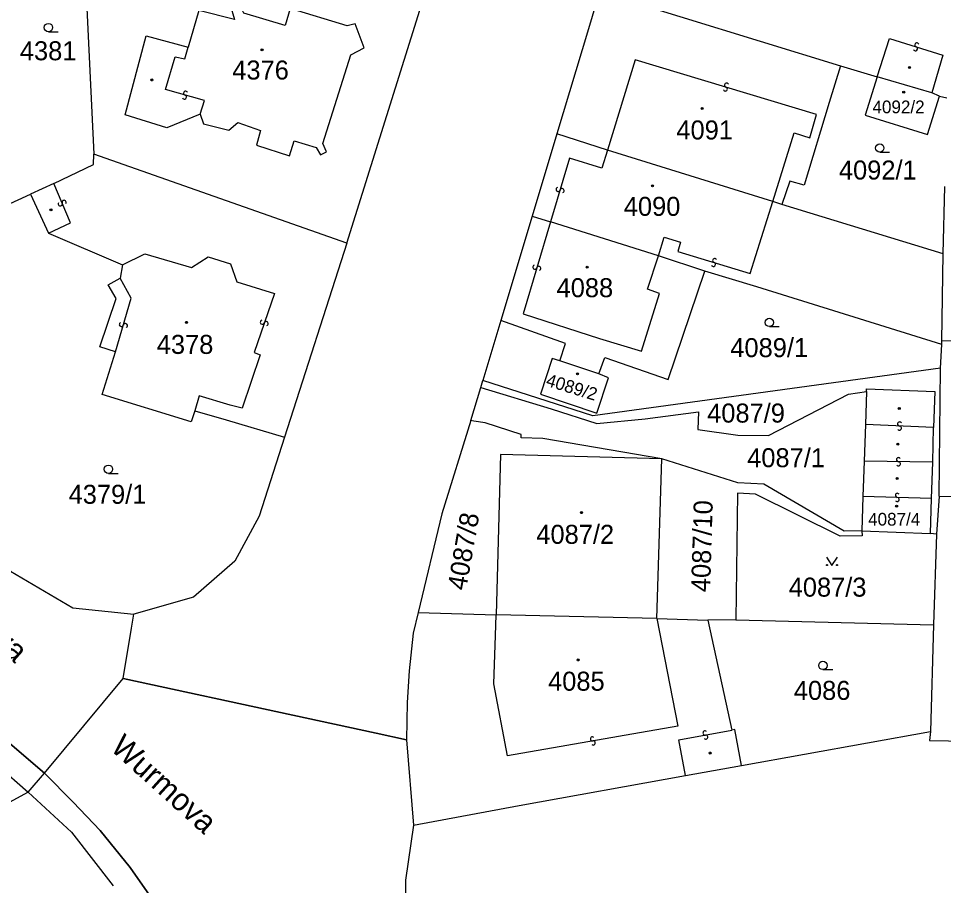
# Model space of a CAD drawing. Extents: x -600391 to -599491, y -1160176 to -1159402.
# Drawn here: x -600028.7 to -599946, y -1159661.1 to -1159583.6 of the extents above; entities that cross this region are included whole.
import ezdxf

# ---------------------------------------------------------------- set-up
doc = ezdxf.new("R2010")
doc.units = 0
for name, color, linetype in [('Level 1', 7, 'Continuous'), ('Level 11', 7, 'Continuous'), ('Level 13', 7, 'Continuous'), ('Level 3', 7, 'Continuous'), ('Level 4', 7, 'Continuous'), ('Level 5', 7, 'Continuous')]:
    doc.layers.add(name, color=color, linetype=linetype)

msp = doc.modelspace()

# ---------------------------------------------------------------- linework, layer by layer
at = {"layer": 'Level 1'}
for points in [[(-600084.15, -1159543.08), (-600050.91, -1159613.18), (-600035.85, -1159643.34), (-600030.3, -1159647.69), (-600026.35, -1159651.08), (-600019.33, -1159642.61)], [(-600023.03, -1159573.34), (-600021.95, -1159595.72)], [(-599976.73, -1159581.2), (-599977.73, -1159584.52), (-599980.55, -1159593.91)], [(-599976.73, -1159581.2), (-599955.2, -1159587.84)], [(-600012.45, -1159592.15), (-600012.13, -1159593.03), (-600009.89, -1159593.6), (-600009.07, -1159592.91), (-600007.05, -1159593.62), (-600007.4, -1159594.93), (-600004.46, -1159595.87), (-600004.05, -1159594.53), (-600002.07, -1159595.14), (-600001.69, -1159595.79), (-600001.14, -1159595.51), (-600001.48, -1159594.79), (-599998.96, -1159586.84), (-599997.79, -1159586.22), (-599998.6, -1159584.08), (-599999.3, -1159584.27), (-600004.4, -1159582.72), (-600004.84, -1159584.23), (-600008.53, -1159583.13), (-600009.05, -1159582.11), (-600009.77, -1159582.37), (-600009.37, -1159583.68), (-600012.57, -1159582.9), (-600013.52, -1159586.18)], [(-599999.32, -1159603.7), (-599992.79, -1159582.85)], [(-600012.45, -1159592.15), (-600015.43, -1159593.37), (-600019.16, -1159592.23), (-600017.27, -1159585.15), (-600013.52, -1159586.18)], [(-599955.2, -1159587.84), (-599956.21, -1159591.11), (-599958.46, -1159598.51), (-599959.72, -1159598.14), (-599960.43, -1159600.22)], [(-599955.2, -1159587.84), (-599951.92, -1159588.83)], [(-599951.92, -1159588.83), (-599952.98, -1159592.24), (-599947.42, -1159593.98), (-599946.34, -1159590.54)], [(-599947.03, -1159590.26), (-599951.92, -1159588.83)], [(-599946.34, -1159590.54), (-599947.03, -1159590.26)], [(-599946.34, -1159590.54), (-599945.69, -1159590.69)], [(-599980.55, -1159593.91), (-599982.75, -1159601.27)], [(-599976.03, -1159595.38), (-599980.55, -1159593.91)], [(-600025.51, -1159598.35), (-600021.98, -1159596.67), (-600021.95, -1159595.72)], [(-599999.32, -1159603.7), (-600021.95, -1159595.72)], [(-599961.25, -1159599.97), (-599976.03, -1159595.38)], [(-600025.51, -1159598.35), (-600027.62, -1159599.31)], [(-599946.01, -1159604.63), (-599945.86, -1159598.63)], [(-600042.97, -1159606.33), (-600027.62, -1159599.31)], [(-600027.62, -1159599.31), (-600026.01, -1159602.79)], [(-599960.43, -1159600.22), (-599961.25, -1159599.97)], [(-599946.01, -1159604.63), (-599960.43, -1159600.22)], [(-599982.75, -1159601.27), (-599985.57, -1159610.6)], [(-599982.75, -1159601.27), (-599981.12, -1159601.77)], [(-599971.48, -1159604.82), (-599981.12, -1159601.77)], [(-600026.01, -1159602.79), (-600019.37, -1159605.63)], [(-599999.32, -1159603.7), (-600004.9, -1159621.04)], [(-599967.32, -1159606.18), (-599971.48, -1159604.82)], [(-599946.13, -1159612.42), (-599946.01, -1159604.63)], [(-600019.37, -1159605.63), (-600019.6, -1159606.83)], [(-600042.97, -1159606.33), (-600032.49, -1159628.9), (-600029.4, -1159633.02), (-600023.82, -1159636.28), (-600018.38, -1159636.85)], [(-599976.8, -1159615.37), (-599976.27, -1159613.9), (-599970.6, -1159615.88), (-599967.32, -1159606.18)], [(-599946.13, -1159612.76), (-599962.69, -1159607.59), (-599967.32, -1159606.18)], [(-600020.01, -1159613.41), (-600021.42, -1159612.95), (-600019.96, -1159608.65), (-600020.66, -1159607.42), (-600019.6, -1159606.83)], [(-599985.57, -1159610.6), (-599987.16, -1159615.96)], [(-599980.29, -1159614.22), (-599979.77, -1159612.65), (-599985.57, -1159610.6)], [(-599946.13, -1159612.76), (-599946.13, -1159612.42)], [(-599919.38, -1159612.92), (-599946.13, -1159612.42)], [(-599946.25, -1159614.86), (-599946.13, -1159612.76)], [(-600012.92, -1159618.67), (-600013.26, -1159619.65), (-600021.2, -1159617.23), (-600020.01, -1159613.41)], [(-599980.29, -1159614.22), (-599980.98, -1159613.99), (-599982.01, -1159617.18), (-599976.98, -1159618.89), (-599975.95, -1159615.72), (-599976.8, -1159615.37)], [(-599946.25, -1159614.86), (-599977.34, -1159619.14), (-599987.16, -1159615.96)], [(-599976.8, -1159615.37), (-599980.29, -1159614.22)], [(-599946.38, -1159626.32), (-599946.25, -1159614.86)], [(-599987.35, -1159616.58), (-599987.16, -1159615.96)], [(-599988.26, -1159619.53), (-599987.35, -1159616.58)], [(-599987.35, -1159616.58), (-599981.06, -1159618.51), (-599976.97, -1159619.81), (-599972.67, -1159619.38), (-599967.9, -1159618.77), (-599967.94, -1159620.35), (-599964.37, -1159620.84), (-599961.64, -1159620.89), (-599954.47, -1159617.19), (-599952.88, -1159616.96)], [(-599952.88, -1159616.96), (-599952.95, -1159619.91)], [(-599952.88, -1159616.96), (-599952.87, -1159616.72), (-599946.77, -1159616.94), (-599946.88, -1159620.18)], [(-600012.92, -1159618.67), (-600010.13, -1159619.47), (-600004.9, -1159621.04)], [(-599988.26, -1159619.53), (-599990.83, -1159627.9), (-599992.95, -1159636.71)], [(-599971.17, -1159622.98), (-599981.82, -1159621.14), (-599983.76, -1159621.08), (-599983.74, -1159620.8), (-599986.96, -1159619.74), (-599987.99, -1159619.61), (-599988.26, -1159619.53)], [(-599952.95, -1159619.91), (-599953.09, -1159623.19)], [(-599946.94, -1159623.27), (-599946.88, -1159620.18)], [(-600004.9, -1159621.04), (-600007.17, -1159628.09), (-600009.35, -1159632.12), (-600013.05, -1159635.33), (-600018.38, -1159636.85)], [(-599971.17, -1159622.98), (-599985.6, -1159622.59), (-599985.99, -1159636.92)], [(-599971.62, -1159637.24), (-599971.17, -1159622.98)], [(-599953.29, -1159629.42), (-599954.88, -1159629.43), (-599962.05, -1159625.23), (-599964.39, -1159625.12), (-599971.17, -1159622.98)], [(-599953.09, -1159623.19), (-599953.19, -1159626.33)], [(-599947.05, -1159626.52), (-599946.94, -1159623.27)], [(-599953.29, -1159629.42), (-599953.27, -1159629.86), (-599955.22, -1159629.87), (-599962.81, -1159626.14), (-599964.41, -1159626.04), (-599964.56, -1159637.36)], [(-599953.19, -1159626.33), (-599953.29, -1159629.42)], [(-599946.38, -1159626.32), (-599946.62, -1159629.69)], [(-599946.38, -1159626.32), (-599930.01, -1159626.62)], [(-599947.15, -1159629.66), (-599947.05, -1159626.52)], [(-599953.29, -1159629.42), (-599947.15, -1159629.66)], [(-599946.62, -1159629.69), (-599947.15, -1159629.66)], [(-599946.62, -1159629.69), (-599946.88, -1159637.81)], [(-600019.33, -1159642.61), (-600018.59, -1159638.1), (-600018.38, -1159636.85)], [(-599992.95, -1159636.71), (-599993.39, -1159638.56), (-599993.77, -1159641.91), (-599993.94, -1159644.74), (-599994, -1159648.08)], [(-599992.95, -1159636.71), (-599985.99, -1159636.92)], [(-599971.62, -1159637.24), (-599985.99, -1159636.92)], [(-599971.62, -1159637.24), (-599967.07, -1159637.39)], [(-599964.56, -1159637.36), (-599967.07, -1159637.39)], [(-599967.07, -1159637.39), (-599964.9, -1159647.23)], [(-599964.56, -1159637.36), (-599946.88, -1159637.81)], [(-599946.88, -1159637.81), (-599947.14, -1159647.36)], [(-600015.71, -1159663.78), (-600018.7, -1159659.49), (-600021.39, -1159656.2), (-600023.79, -1159653.65), (-600026.35, -1159651.08), (-600019.33, -1159642.61), (-600004.15, -1159645.89), (-599996.7, -1159647.5), (-599994, -1159648.08), (-599993.37, -1159655.71)], [(-599994, -1159648.08), (-599996.7, -1159647.5), (-600004.15, -1159645.89), (-600019.33, -1159642.61)], [(-600026.35, -1159651.08), (-600030.3, -1159647.69), (-600035.85, -1159643.34)], [(-599993.37, -1159655.71), (-599983.92, -1159653.96), (-599969.05, -1159651.28), (-599964.06, -1159650.4), (-599947.14, -1159647.36), (-599947.25, -1159648.16), (-599930.29, -1159648.46), (-599924.07, -1159648.56), (-599921.27, -1159648.58), (-599903.15, -1159648.95)], [(-599964.06, -1159650.4), (-599964.63, -1159647.18), (-599964.9, -1159647.23)], [(-599964.06, -1159650.4), (-599947.14, -1159647.36)], [(-599947.14, -1159647.36), (-599947.25, -1159648.16), (-599930.29, -1159648.46)], [(-599994, -1159648.08), (-599993.37, -1159655.71), (-599983.92, -1159653.96), (-599969.05, -1159651.28)], [(-600030.57, -1159650.4), (-600027.83, -1159652.78)], [(-599969.05, -1159651.28), (-599964.06, -1159650.4)], [(-600027.83, -1159652.78), (-600026.35, -1159651.08)], [(-600026.35, -1159651.08), (-600023.79, -1159653.65), (-600021.39, -1159656.2), (-600018.7, -1159659.49), (-600015.71, -1159663.78), (-600012.85, -1159668.55), (-599985.71, -1159716.21)], [(-600027.83, -1159652.78), (-600030.16, -1159654.06), (-600037.5, -1159658.14)], [(-600027.83, -1159652.78), (-600023.93, -1159656.35), (-600020.23, -1159661.15)], [(-599993.37, -1159655.71), (-599994.09, -1159660.65), (-599994.05, -1159663.73)]]:
    msp.add_lwpolyline(points, dxfattribs=at)
at = {"layer": 'Level 13'}
for centre, start, end in [((-599948.383, -1159585.965), 19.84143, 251.93943), ((-599948.496, -1159586.315), 199.62697, 72.21697), ((-599965.495, -1159589.906), 200.58598, 72.68397), ((-599965.386, -1159589.554), 20.37152, 252.96152), ((-600013.852, -1159590.637), 201.44915, 73.54714), ((-600013.749, -1159590.283), 21.23469, 253.82469), ((-599980.446, -1159598.886), 110.46831, 343.05831), ((-599980.094, -1159598.995), 290.68276, 162.78076), ((-600024.6, -1159600.039), 329.96282, 202.55282), ((-600024.941, -1159600.18), 150.17728, 22.27527), ((-599982.526, -1159605.837), 110.53561, 343.12561), ((-599982.174, -1159605.944), 290.75007, 162.84807), ((-599966.554, -1159605.596), 200.30479, 72.89479), ((-599966.445, -1159605.244), 20.51925, 252.61725), ((-600006.884, -1159610.76), 108.36665, 340.95665), ((-600006.536, -1159610.881), 288.58111, 160.67911), ((-600019.487, -1159610.957), 111.2226, 343.32059), ((-600019.133, -1159611.062), 291.00814, 163.59814), ((-599949.911, -1159619.856), 34.61138, 267.20138), ((-599949.93, -1159620.224), 214.82584, 86.92383), ((-599950.017, -1159623.046), 36.41301, 269.00301), ((-599950.024, -1159623.414), 216.62746, 88.72546), ((-599950.113, -1159626.236), 35.38585, 267.97585), ((-599950.127, -1159626.604), 215.6003, 87.6983), ((-599977.371, -1159648.009), 47.06536, 279.65536), ((-599967.311, -1159647.478), 47.49741, 279.5954), ((-599967.248, -1159647.841), 227.28295, 99.87295), ((-599977.31, -1159648.372), 227.27981, 99.37781)]:
    msp.add_arc(centre, 0.184, start, end, dxfattribs=at)
at = {"layer": 'Level 3'}
for points in [[(-599951.92, -1159588.83), (-599950.83, -1159585.38), (-599946.05, -1159586.89), (-599947.03, -1159590.26)], [(-600012.45, -1159592.15), (-600012.06, -1159590.95), (-600015.53, -1159589.96), (-600014.69, -1159587.02), (-600013.8, -1159587.22), (-600013.52, -1159586.18)], [(-599961.25, -1159599.97), (-599959.33, -1159593.83), (-599957.94, -1159594.27), (-599957.33, -1159592.18), (-599973.54, -1159587.29), (-599976.03, -1159595.38)], [(-599976.03, -1159595.38), (-599976.54, -1159596.98), (-599979.42, -1159596.1), (-599981.12, -1159601.77)], [(-600026.01, -1159602.79), (-600024.03, -1159601.87), (-600025.51, -1159598.35)], [(-599971.48, -1159604.82), (-599970.95, -1159603.16), (-599969.5, -1159603.61), (-599969.74, -1159604.44), (-599963.27, -1159606.4), (-599961.25, -1159599.97)], [(-599981.12, -1159601.77), (-599983.58, -1159610.01), (-599976.75, -1159612.2), (-599972.99, -1159613.35), (-599971.38, -1159608.2), (-599972.44, -1159607.8), (-599971.48, -1159604.82)], [(-600019.37, -1159605.63), (-600017.39, -1159604.65), (-600013.22, -1159605.87), (-600011.74, -1159604.92), (-600009.72, -1159605.55), (-600009.15, -1159607.15), (-600005.81, -1159608.18), (-600007.61, -1159613.47), (-600007.07, -1159613.66), (-600008.68, -1159618.45), (-600009.77, -1159618.17), (-600012.54, -1159617.35), (-600012.92, -1159618.67)], [(-600020.01, -1159613.41), (-600018.62, -1159608.61), (-600019.6, -1159606.83)], [(-599946.88, -1159620.18), (-599952.95, -1159619.91)], [(-599946.94, -1159623.27), (-599953.09, -1159623.19)], [(-599947.05, -1159626.52), (-599953.19, -1159626.33)], [(-599971.62, -1159637.24), (-599969.73, -1159646.86), (-599984.96, -1159649.52), (-599986.2, -1159643.09), (-599986.03, -1159638.75), (-599985.99, -1159636.92)], [(-599969.05, -1159651.28), (-599969.66, -1159648.08), (-599964.9, -1159647.23)]]:
    msp.add_lwpolyline(points, dxfattribs=at)
at = {"layer": 'Level 5'}
for p, q in [((-600026.01, -1159584.79), (-600025.135, -1159584.79)), ((-599951.69, -1159595.56), (-599950.815, -1159595.56)), ((-599961.56, -1159611.15), (-599960.685, -1159611.15)), ((-600020.64, -1159624.28), (-600019.765, -1159624.28)), ((-599956.77, -1159641.81), (-599955.895, -1159641.81))]:
    msp.add_line(p, q, dxfattribs=at)
msp.add_lwpolyline([(-599956.461, -1159631.77), (-599955.96, -1159632.52), (-599955.46, -1159631.77)], dxfattribs=at)
for centre, radius in [((-600026.01, -1159584.415), 0.375), ((-600006.91, -1159586.41), 0.09), ((-600006.91, -1159586.41), 0.0521), ((-599949.03, -1159587.99), 0.09), ((-599949.03, -1159587.99), 0.0521), ((-600016.77, -1159589.1), 0.09), ((-600016.77, -1159589.1), 0.0521), ((-599949.55, -1159590.19), 0.09), ((-599949.55, -1159590.19), 0.0521), ((-599967.56, -1159591.64), 0.09), ((-599967.56, -1159591.64), 0.0521), ((-599951.69, -1159595.185), 0.375), ((-599972.01, -1159598.56), 0.09), ((-599972.01, -1159598.56), 0.0521), ((-600025.78, -1159600.71), 0.09), ((-600025.78, -1159600.71), 0.0521), ((-599977.84, -1159605.84), 0.09), ((-599977.84, -1159605.84), 0.0521), ((-600013.66, -1159610.77), 0.09), ((-600013.66, -1159610.77), 0.0521), ((-599961.56, -1159610.775), 0.375), ((-599978.7, -1159615.37), 0.09), ((-599978.7, -1159615.37), 0.0521), ((-599949.94, -1159618.46), 0.09), ((-599949.94, -1159618.46), 0.0521), ((-599950.08, -1159621.65), 0.09), ((-599950.08, -1159621.65), 0.0521), ((-600020.64, -1159623.905), 0.375), ((-599950.13, -1159624.72), 0.09), ((-599950.13, -1159624.72), 0.0521), ((-599950.18, -1159627.2), 0.09), ((-599950.18, -1159627.2), 0.0521), ((-599978.36, -1159627.78), 0.09), ((-599978.36, -1159627.78), 0.0521), ((-599956.41, -1159632.47), 0.05), ((-599955.511, -1159632.47), 0.05), ((-599978.64, -1159640.95), 0.09), ((-599978.64, -1159640.95), 0.0521), ((-599956.77, -1159641.435), 0.375), ((-599966.86, -1159649.27), 0.09), ((-599966.86, -1159649.27), 0.0521)]:
    msp.add_circle(centre, radius, dxfattribs=at)

# ---------------------------------------------------------------- texts
at = {"layer": 'Level 11'}
for p in [(-600037.474, -1159633.618), (-600020.564, -1159648.93)]:
    msp.add_text('Wurmova', height=2, rotation=317.83967, dxfattribs=at).set_placement(p)
at = {"layer": 'Level 4'}
for s, height, p in [('4381', 1.7, (-600028.56, -1159587.34)), ('4376', 1.7, (-600009.57, -1159589.06)), ('4092/2', 1.14, (-599952.34, -1159592.08)), ('4091', 1.7, (-599969.87, -1159594.42)), ('4092/1', 1.7, (-599955.34, -1159598)), ('4090', 1.7, (-599974.57, -1159601.25)), ('4088', 1.7, (-599980.58, -1159608.52)), ('4378', 1.7, (-600016.32, -1159613.59)), ('4089/1', 1.7, (-599965.05, -1159613.88)), ('4087/9', 1.7, (-599967.119, -1159619.73)), ('4087/1', 1.7, (-599963.54, -1159623.72)), ('4379/1', 1.7, (-600024.202, -1159626.99)), ('4087/4', 1.14, (-599952.73, -1159628.94)), ('4087/2', 1.7, (-599982.39, -1159630.57)), ('4087/3', 1.7, (-599959.83, -1159635.29)), ('4085', 1.7, (-599981.34, -1159643.7)), ('4086', 1.7, (-599959.37, -1159644.52))]:
    msp.add_text(s, height=height, dxfattribs=at).set_placement(p)
for s, height, rotation, p in [('4089/2', 1.14, 342.8973, (-599981.61, -1159616.42)), ('4087/10', 1.7, 88.27191, (-599966.86, -1159634.908)), ('4087/8', 1.7, 80.1, (-599988.673, -1159634.798))]:
    msp.add_text(s, height=height, rotation=rotation, dxfattribs=at).set_placement(p)

doc.saveas('drawing.dxf')
